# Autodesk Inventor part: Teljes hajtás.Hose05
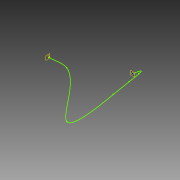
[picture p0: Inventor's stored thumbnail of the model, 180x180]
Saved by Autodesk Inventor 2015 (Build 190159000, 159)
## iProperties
_PSKETCH_SNAP: False
_PSKETCH_RSNP: False
_BASENETWORK_NOTAUTODIMENSION: False
StyleName: _Piping Style 20
Created: 2013-02
Part Number: Teljes hajtás.Hose05
Material: Generic
Document SubType Name: Modeling
Designer: Marci
Density: 1 g/cm^3
Appearance: Default
ActiveState: True
Angle: UnInitValue
BendRadius: 0.500 in
CouplingKey: UnInitValue
DefaultBendRadius: UnInitValue
Diameter: 1/4
DiameterType: Nominal
Elbow45Key: UnInitValue
Elbow90Key: UnInitValue
ElbowCustomKey: UnInitValue
Ending: UnInitValue
FittingMaterial: UnInitValue
FittingStandard: UnInitValue
FlangeKey: UnInitValue
Gap: UnInitValue
GasketKey: UnInitValue
ID: 0,635
IsButtWelded: UnInitValue
IsFlanged: UnInitValue
IsSelfDraining: UnInitValue
Material: UnInitValue
MixedUnits: UnInitValue
Name: Hydraulic Hose - No Fittings
OD: 1,4986
PipeKey: v3#d489867e-ac9b-47ea-b952-0a1b885f66be#1
PipeType: Flexible Hose
PipingComponentColor: Blue - Wall Paint - Glossy
RoundUpValue: 0.125 in
RouteDirection45: UnInitValue
RouteDirection90: UnInitValue
Schedule: ID=0.25
ShowGap: UnInitValue
Standard: UnInitValue
SuppressEndFitting: True
SuppressStartFitting: True
UseFlangsForCouplings: UnInitValue
UseSubASM: True
_ComponentInfo: <CS><C N="Pipe" R="0,749300" OR="0,749300" IR="0,317500" PL="PL" PartType="pipe" SymKey="" PN="Parker hidraulikatömlő - No Skive 1/4"><CO N="1"><FE V="0"/><FD V
Author: Marci
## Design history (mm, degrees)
workpoint "Work Point1"
workpoint "Work Point2"
workplane "Work Plane1"
workpoint "Work Point3"
workplane "Work Plane2"
sketch "3D Sketch1" dims "d0" = 10, "d1" = 0.1 (derived), "d2" = 10, "d3" = 0.1 (derived)
other parameters: "B" = 12.7 [user parameter]
